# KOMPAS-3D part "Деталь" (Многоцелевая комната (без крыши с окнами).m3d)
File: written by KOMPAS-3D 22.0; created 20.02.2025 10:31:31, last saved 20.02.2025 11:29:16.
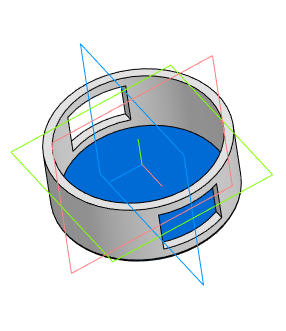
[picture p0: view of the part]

Document properties: Автор: Пользователь Windows; Полное имя файла: C:\Users\Student\Documents\Картошечка\База Сабнатика\Многоцелевая комната (без крыши с окнами).m3d

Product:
- Part/product: Деталь
    Масса: 0.104622

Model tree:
1. Эскиз:3
2. Элемент вращения:1
     Угол 1 = 360
3. Скругление:1  (with: Элемент вращения:1)
     Радиус = 1
4. Эскиз:4  (with: Элемент вращения:1)
5. Элемент выдавливания:1
     Расстояние 2 = 6.1
6. Эскиз:5  (with: Элемент выдавливания:1)
7. Элемент выдавливания:2
     Расстояние 2 = 19
8. Эскиз:6
9. Элемент выдавливания:3
     Расстояние 1 = 25; Расстояние 2 = 25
